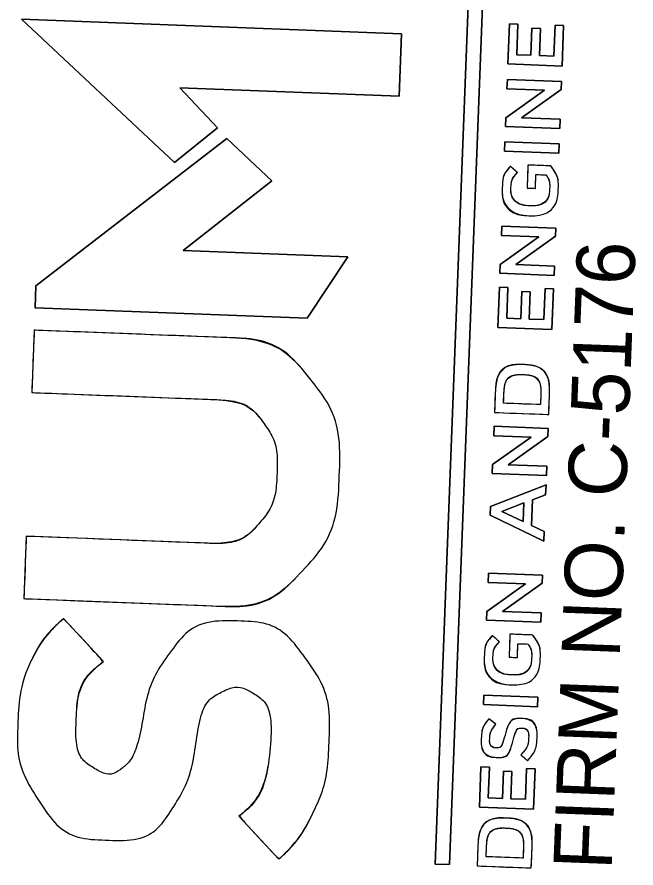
# Model space of a CAD drawing. Extents: x 1654773 to 2116434, y 680831 to 888488.
# Drawn here: x 2099592.9 to 2099858.3, y 685725.9 to 686090.8 of the extents above; entities that cross this region are included whole.
import ezdxf

# ---------------------------------------------------------------- set-up
doc = ezdxf.new("R2010")
doc.units = 0
doc.layers.add('Old_Level_3', color=7, linetype='Continuous')

msp = doc.modelspace()

# ---------------------------------------------------------------- linework, layer by layer
at = {"layer": 'Old_Level_3'}
for p, q in [((2099807.44, 686024.06), (2099804.45, 686026.77)), ((2099812.68, 686009.83), (2099812.61, 686009.84)), ((2099812.51, 686005.56), (2099812.58, 686005.56)), ((2099810.06, 685941.73), (2099810, 685941.73)), ((2099809.9, 685937.46), (2099809.97, 685937.45)), ((2099629.93, 685814.4), (2099612.81, 685832.86)), ((2099799.72, 685822.88), (2099796.74, 685825.58)), ((2099804.96, 685808.65), (2099804.89, 685808.65)), ((2099804.8, 685804.38), (2099804.86, 685804.38)), ((2099798.2, 685787.46), (2099795.2, 685789.77)), ((2099809.26, 685789.92), (2099809.19, 685789.92)), ((2099809.43, 685785.84), (2099809.5, 685785.83)), ((2099798.25, 685777.37), (2099798.18, 685777.38)), ((2099798.39, 685773.29), (2099798.45, 685773.29)), ((2099808.96, 685774.41), (2099811.79, 685771.85)), ((2099688.04, 685748.08), (2099705.17, 685729.62)), ((2099802.61, 685747.27), (2099802.54, 685747.27)), ((2099802.44, 685743), (2099802.51, 685743))]:
    msp.add_line(p, q, dxfattribs=at)
for points in [[(2099803.18, 686374.77), (2099778.35, 685727.33), (2099772.17, 685727.56), (2099797.01, 686375.01), (2099803.18, 686374.77)], [(2099797.01, 686375.01), (2099772.17, 685727.56), (2099778.35, 685727.33), (2099803.18, 686374.77), (2099797.01, 686375.01)], [(2099594.75, 686089.78), (2099757.71, 686083.53), (2099756.68, 686056.81), (2099662.69, 686060.42), (2099678.88, 686043.23), (2099660.43, 686028.35), (2099594.75, 686089.78)], [(2099660.43, 686028.35), (2099678.88, 686043.23), (2099662.69, 686060.42), (2099756.68, 686056.81), (2099757.71, 686083.53), (2099594.75, 686089.78), (2099660.43, 686028.35)], [(2099803.38, 686070.64), (2099804.04, 686087.83), (2099807.69, 686087.69), (2099807.19, 686074.57), (2099813.22, 686074.34), (2099813.67, 686085.96), (2099817.32, 686085.82), (2099816.87, 686074.2), (2099823.11, 686073.96), (2099823.62, 686087.24), (2099827.27, 686087.1), (2099826.6, 686069.75), (2099803.38, 686070.64)], [(2099826.6, 686069.75), (2099827.27, 686087.1), (2099823.62, 686087.24), (2099823.11, 686073.96), (2099816.87, 686074.2), (2099817.32, 686085.82), (2099813.67, 686085.96), (2099813.22, 686074.34), (2099807.19, 686074.57), (2099807.69, 686087.69), (2099804.04, 686087.83), (2099803.38, 686070.64), (2099826.6, 686069.75)], [(2099802.35, 686043.82), (2099802.5, 686047.6), (2099819.03, 686059.4), (2099802.97, 686060.01), (2099803.13, 686064.02), (2099826.35, 686063.13), (2099826.22, 686059.72), (2099809.21, 686047.57), (2099825.73, 686046.94), (2099825.57, 686042.93), (2099802.35, 686043.82)], [(2099825.57, 686042.93), (2099825.73, 686046.94), (2099809.21, 686047.57), (2099826.22, 686059.72), (2099826.35, 686063.13), (2099803.13, 686064.02), (2099802.97, 686060.01), (2099819.03, 686059.4), (2099802.5, 686047.6), (2099802.35, 686043.82), (2099825.57, 686042.93)], [(2099600.98, 685975.48), (2099682.8, 686038.73), (2099702.08, 686020.46), (2099664.15, 685990.59), (2099734.72, 685987.88), (2099717.29, 685961.58), (2099600.62, 685966.05), (2099600.98, 685975.48)], [(2099600.62, 685966.05), (2099717.29, 685961.58), (2099734.72, 685987.88), (2099664.15, 685990.59), (2099702.08, 686020.46), (2099682.8, 686038.73), (2099600.98, 685975.48), (2099600.62, 685966.05)], [(2099801.94, 686033.22), (2099802.1, 686037.3), (2099825.32, 686036.41), (2099825.17, 686032.33), (2099801.94, 686033.22)], [(2099825.17, 686032.33), (2099825.32, 686036.41), (2099802.1, 686037.3), (2099801.94, 686033.22), (2099825.17, 686032.33)], [(2099821.74, 686026.93), (2099811.98, 686027.31), (2099811.61, 686017.44), (2099815.15, 686017.3), (2099815.38, 686023.23), (2099819.73, 686023.06)], [(2099799.94, 685980.88), (2099800.08, 685984.65), (2099816.61, 685996.45), (2099800.56, 685997.07), (2099800.71, 686001.08), (2099823.93, 686000.19), (2099823.8, 685996.78), (2099806.79, 685984.63), (2099823.31, 685983.99), (2099823.16, 685979.99), (2099799.94, 685980.88)], [(2099823.16, 685979.99), (2099823.31, 685983.99), (2099806.79, 685984.63), (2099823.8, 685996.78), (2099823.93, 686000.19), (2099800.71, 686001.08), (2099800.56, 685997.07), (2099816.61, 685996.45), (2099800.08, 685984.65), (2099799.94, 685980.88), (2099823.16, 685979.99)], [(2099799.05, 685957.7), (2099799.71, 685974.89), (2099803.36, 685974.75), (2099802.85, 685961.63), (2099808.89, 685961.4), (2099809.34, 685973.02), (2099812.99, 685972.88), (2099812.54, 685961.26), (2099818.78, 685961.02), (2099819.29, 685974.3), (2099822.94, 685974.16), (2099822.27, 685956.81), (2099799.05, 685957.7)], [(2099822.27, 685956.81), (2099822.94, 685974.16), (2099819.29, 685974.3), (2099818.78, 685961.02), (2099812.54, 685961.26), (2099812.99, 685972.88), (2099809.34, 685973.02), (2099808.89, 685961.4), (2099802.85, 685961.63), (2099803.36, 685974.75), (2099799.71, 685974.89), (2099799.05, 685957.7), (2099822.27, 685956.81)], [(2099684.31, 685953.24), (2099600.25, 685956.46), (2099599.23, 685929.74), (2099676.15, 685926.79)], [(2099797.98, 685929.85), (2099797.65, 685921.21), (2099820.87, 685920.32), (2099821.2, 685928.96)], [(2099817.49, 685929.11), (2099817.31, 685924.54), (2099801.52, 685925.14), (2099801.69, 685929.71)], [(2099796.65, 685895.05), (2099796.79, 685898.83), (2099813.32, 685910.63), (2099797.27, 685911.24), (2099797.42, 685915.26), (2099820.64, 685914.37), (2099820.51, 685910.95), (2099803.5, 685898.8), (2099820.02, 685898.17), (2099819.87, 685894.16), (2099796.65, 685895.05)], [(2099819.87, 685894.16), (2099820.02, 685898.17), (2099803.5, 685898.8), (2099820.51, 685910.95), (2099820.64, 685914.37), (2099797.42, 685915.26), (2099797.27, 685911.24), (2099813.32, 685910.63), (2099796.79, 685898.83), (2099796.65, 685895.05), (2099819.87, 685894.16)], [(2099795.79, 685877.11), (2099795.94, 685880.89), (2099819.72, 685890.2), (2099819.55, 685885.89), (2099813.85, 685883.75), (2099813.43, 685872.79), (2099818.95, 685870.19), (2099818.79, 685866.02), (2099795.79, 685877.11)], [(2099818.79, 685866.02), (2099818.95, 685870.19), (2099813.43, 685872.79), (2099813.85, 685883.75), (2099819.55, 685885.89), (2099819.72, 685890.2), (2099795.94, 685880.89), (2099795.79, 685877.11), (2099818.79, 685866.02)], [(2099810.18, 685882.4), (2099800.74, 685878.75), (2099809.87, 685874.42), (2099810.18, 685882.4)], [(2099809.87, 685874.42), (2099800.74, 685878.75), (2099810.18, 685882.4), (2099809.87, 685874.42)], [(2099673.79, 685865.14), (2099596.86, 685868.09), (2099595.84, 685841.36), (2099679.89, 685838.14)], [(2099794.23, 685832.14), (2099794.38, 685835.91), (2099810.91, 685847.72), (2099794.85, 685848.34), (2099795.01, 685852.34), (2099818.23, 685851.45), (2099818.1, 685848.04), (2099801.09, 685835.89), (2099817.61, 685835.26), (2099817.45, 685831.25), (2099794.23, 685832.14)], [(2099817.45, 685831.25), (2099817.61, 685835.26), (2099801.09, 685835.89), (2099818.1, 685848.04), (2099818.23, 685851.45), (2099795.01, 685852.34), (2099794.85, 685848.34), (2099810.91, 685847.72), (2099794.38, 685835.91), (2099794.23, 685832.14), (2099817.45, 685831.25)], [(2099814.02, 685825.75), (2099804.27, 685826.12), (2099803.89, 685816.25), (2099807.44, 685816.12), (2099807.67, 685822.05), (2099812.01, 685821.88)], [(2099792.84, 685795.92), (2099793, 685799.99), (2099816.22, 685799.1), (2099816.07, 685795.03), (2099792.84, 685795.92)], [(2099816.07, 685795.03), (2099816.22, 685799.1), (2099793, 685799.99), (2099792.84, 685795.92), (2099816.07, 685795.03)], [(2099791.16, 685751.98), (2099791.82, 685769.17), (2099795.47, 685769.03), (2099794.96, 685755.91), (2099801, 685755.68), (2099801.45, 685767.31), (2099805.1, 685767.17), (2099804.65, 685755.54), (2099810.89, 685755.3), (2099811.4, 685768.58), (2099815.05, 685768.44), (2099814.38, 685751.09), (2099791.16, 685751.98)], [(2099814.38, 685751.09), (2099815.05, 685768.44), (2099811.4, 685768.58), (2099810.89, 685755.3), (2099804.65, 685755.54), (2099805.1, 685767.17), (2099801.45, 685767.31), (2099801, 685755.68), (2099794.96, 685755.91), (2099795.47, 685769.03), (2099791.82, 685769.17), (2099791.16, 685751.98), (2099814.38, 685751.09)], [(2099790.52, 685735.4), (2099790.19, 685726.75), (2099813.41, 685725.86), (2099813.74, 685734.51)], [(2099810.03, 685734.65), (2099809.85, 685730.08), (2099794.06, 685730.68), (2099794.24, 685735.25)]]:
    msp.add_lwpolyline(points, dxfattribs=at)
for points, degree in [([(2099812.58, 686005.56), (2099812.58, 686005.56), (2099812.51, 686005.56), (2099812.51, 686005.56), (2099806.01, 686005.81), (2099800.69, 686010.99), (2099800.96, 686017.98), (2099801.12, 686022.02), (2099802.34, 686024.46), (2099804.45, 686026.77), (2099804.45, 686026.77), (2099807.44, 686024.06), (2099807.44, 686024.06), (2099805.85, 686022.34), (2099804.82, 686020.62), (2099804.7, 686017.67), (2099804.54, 686013.4), (2099808.16, 686010.01), (2099812.61, 686009.84), (2099812.61, 686009.84), (2099812.68, 686009.83), (2099812.68, 686009.83), (2099817.45, 686009.65), (2099821.09, 686012.66), (2099821.27, 686017.4), (2099821.36, 686019.58), (2099820.73, 686021.6), (2099819.73, 686023.06), (2099819.73, 686023.06), (2099815.38, 686023.23), (2099815.38, 686023.23), (2099815.38, 686023.23), (2099815.15, 686017.3), (2099815.15, 686017.3), (2099815.15, 686017.3), (2099811.61, 686017.44), (2099811.61, 686017.44), (2099811.61, 686017.44), (2099811.98, 686027.31), (2099811.98, 686027.31), (2099811.98, 686027.31), (2099821.74, 686026.93), (2099821.74, 686026.93), (2099823.61, 686024.58), (2099825.14, 686021.23), (2099824.98, 686017.12), (2099824.7, 686009.87), (2099819.35, 686005.3), (2099812.58, 686005.56)], 3), ([(2099804.45, 686026.77), (2099802.34, 686024.46), (2099801.12, 686022.02), (2099800.96, 686017.98), (2099800.69, 686010.99), (2099806.01, 686005.81), (2099812.51, 686005.56)], 3), ([(2099812.61, 686009.84), (2099808.16, 686010.01), (2099804.54, 686013.4), (2099804.7, 686017.67), (2099804.82, 686020.62), (2099805.85, 686022.34), (2099807.44, 686024.06)], 3), ([(2099812.58, 686005.56), (2099819.35, 686005.3), (2099824.7, 686009.87), (2099824.98, 686017.12), (2099825.14, 686021.23), (2099823.61, 686024.58), (2099821.74, 686026.93)], 3), ([(2099819.73, 686023.06), (2099820.73, 686021.6), (2099821.36, 686019.58), (2099821.27, 686017.4), (2099821.09, 686012.66), (2099817.45, 686009.65), (2099812.68, 686009.83)], 3), ([(2099596.86, 685868.09), (2099596.86, 685868.09), (2099673.79, 685865.14), (2099673.79, 685865.14), (2099683.89, 685864.75), (2099691.42, 685867.49), (2099696.4, 685873.23), (2099701.38, 685878.98), (2099704.04, 685886.33), (2099704.38, 685895.22), (2099704.72, 685904.11), (2099702.62, 685911.28), (2099698.09, 685917.39), (2099693.57, 685923.49), (2099686.26, 685926.41), (2099676.15, 685926.79), (2099676.15, 685926.79), (2099599.23, 685929.74), (2099599.23, 685929.74), (2099599.23, 685929.74), (2099600.25, 685956.46), (2099600.25, 685956.46), (2099600.25, 685956.46), (2099684.31, 685953.24), (2099684.31, 685953.24), (2099697.97, 685952.72), (2099709.34, 685947.12), (2099718.42, 685935.78), (2099727.49, 685924.45), (2099731.73, 685910.66), (2099731.09, 685894.07), (2099730.45, 685877.47), (2099725.17, 685863.86), (2099715.25, 685853.27), (2099705.33, 685842.66), (2099693.55, 685837.62), (2099679.89, 685838.14), (2099679.89, 685838.14), (2099595.84, 685841.36), (2099595.84, 685841.36), (2099595.84, 685841.36), (2099596.86, 685868.09), (2099596.86, 685868.09)], 3), ([(2099679.89, 685838.14), (2099693.55, 685837.62), (2099705.33, 685842.66), (2099715.25, 685853.27), (2099725.17, 685863.86), (2099730.45, 685877.47), (2099731.09, 685894.07), (2099731.73, 685910.66), (2099727.49, 685924.45), (2099718.42, 685935.78), (2099709.34, 685947.12), (2099697.97, 685952.72), (2099684.31, 685953.24)], 3), ([(2099797.65, 685921.21), (2099797.65, 685921.21), (2099797.98, 685929.85), (2099797.98, 685929.85), (2099798.26, 685937.14), (2099803.46, 685941.98), (2099810, 685941.73), (2099810, 685941.73), (2099810.06, 685941.73), (2099810.06, 685941.73), (2099816.6, 685941.48), (2099821.48, 685936.25), (2099821.2, 685928.96), (2099821.2, 685928.96), (2099820.87, 685920.32), (2099820.87, 685920.32), (2099820.87, 685920.32), (2099797.65, 685921.21), (2099797.65, 685921.21)], 3), ([(2099810, 685941.73), (2099803.46, 685941.98), (2099798.26, 685937.14), (2099797.98, 685929.85)], 2), ([(2099821.2, 685928.96), (2099821.48, 685936.25), (2099816.6, 685941.48), (2099810.06, 685941.73)], 2), ([(2099801.52, 685925.14), (2099801.52, 685925.14), (2099817.31, 685924.54), (2099817.31, 685924.54), (2099817.31, 685924.54), (2099817.49, 685929.11), (2099817.49, 685929.11), (2099817.67, 685933.98), (2099814.51, 685937.28), (2099809.97, 685937.45), (2099809.97, 685937.45), (2099809.9, 685937.46), (2099809.9, 685937.46), (2099805.35, 685937.63), (2099801.88, 685934.58), (2099801.69, 685929.71), (2099801.69, 685929.71), (2099801.52, 685925.14), (2099801.52, 685925.14)], 3), ([(2099801.69, 685929.71), (2099801.88, 685934.58), (2099805.35, 685937.63), (2099809.9, 685937.46)], 2), ([(2099809.97, 685937.45), (2099814.51, 685937.28), (2099817.67, 685933.98), (2099817.49, 685929.11)], 2), ([(2099676.15, 685926.79), (2099686.26, 685926.41), (2099693.57, 685923.49), (2099698.09, 685917.39), (2099702.62, 685911.28), (2099704.72, 685904.11), (2099704.38, 685895.22), (2099704.04, 685886.33), (2099701.38, 685878.98), (2099696.4, 685873.23), (2099691.42, 685867.49), (2099683.89, 685864.75), (2099673.79, 685865.14)], 3), ([(2099598.73, 685814.26), (2099601.95, 685820.97), (2099606.64, 685827.17), (2099612.81, 685832.86), (2099612.81, 685832.86), (2099629.93, 685814.4), (2099629.93, 685814.4), (2099622.59, 685808.75), (2099618.7, 685800.6), (2099618.3, 685789.92), (2099617.89, 685779.26), (2099620.15, 685772.34), (2099625.09, 685769.18), (2099630.02, 685766.03), (2099634.32, 685765.87), (2099637.99, 685768.69), (2099641.67, 685771.52), (2099644.6, 685778.23), (2099646.79, 685788.83), (2099648.41, 685800.04), (2099652.51, 685810.13), (2099659.1, 685819.07), (2099665.68, 685828.02), (2099675.8, 685832.22), (2099689.46, 685831.7), (2099700.15, 685831.29), (2099709.16, 685826.04), (2099716.49, 685815.94), (2099723.84, 685805.84), (2099727.26, 685794.26), (2099726.76, 685781.22), (2099726.29, 685768.84), (2099724.11, 685758.56), (2099720.23, 685750.4), (2099716.34, 685742.24), (2099711.32, 685735.31), (2099705.17, 685729.62), (2099705.17, 685729.62), (2099688.04, 685748.08), (2099688.04, 685748.08), (2099695.39, 685753.73), (2099699.93, 685763.65), (2099701.66, 685777.82), (2099702.11, 685789.68), (2099699.87, 685797.17), (2099694.94, 685800.3), (2099690.01, 685803.42), (2099684.96, 685803.61), (2099679.8, 685800.88), (2099674.64, 685798.14), (2099671.25, 685790.86), (2099669.6, 685779.05), (2099668.01, 685768.43), (2099664.37, 685758.78), (2099658.68, 685750.09), (2099653, 685741.41), (2099643.63, 685737.31), (2099630.57, 685737.81), (2099618.76, 685738.27), (2099609.47, 685743.69), (2099602.7, 685754.07), (2099595.93, 685764.44), (2099592.76, 685774.96), (2099593.16, 685785.63), (2099593.64, 685798.02), (2099595.48, 685807.56), (2099598.73, 685814.26)], 3), ([(2099612.81, 685832.86), (2099606.64, 685827.17), (2099601.95, 685820.97), (2099598.73, 685814.26)], 2), ([(2099705.17, 685729.62), (2099711.32, 685735.31), (2099716.34, 685742.24), (2099720.23, 685750.4), (2099724.11, 685758.56), (2099726.29, 685768.84), (2099726.76, 685781.22), (2099727.26, 685794.26), (2099723.84, 685805.84), (2099716.49, 685815.94), (2099709.16, 685826.04), (2099700.15, 685831.29), (2099689.46, 685831.7), (2099675.8, 685832.22), (2099665.68, 685828.02), (2099659.1, 685819.07), (2099652.51, 685810.13), (2099648.41, 685800.04), (2099646.79, 685788.83), (2099644.6, 685778.23), (2099641.67, 685771.52), (2099637.99, 685768.69), (2099634.32, 685765.87), (2099630.02, 685766.03), (2099625.09, 685769.18), (2099620.15, 685772.34), (2099617.89, 685779.26), (2099618.3, 685789.92), (2099618.7, 685800.6), (2099622.59, 685808.75), (2099629.93, 685814.4)], 3), ([(2099804.86, 685804.38), (2099804.86, 685804.38), (2099804.8, 685804.38), (2099804.8, 685804.38), (2099798.29, 685804.63), (2099792.98, 685809.81), (2099793.25, 685816.79), (2099793.4, 685820.84), (2099794.62, 685823.28), (2099796.74, 685825.58), (2099796.74, 685825.58), (2099799.72, 685822.88), (2099799.72, 685822.88), (2099798.13, 685821.15), (2099797.1, 685819.44), (2099796.99, 685816.49), (2099796.82, 685812.21), (2099800.45, 685808.82), (2099804.89, 685808.65), (2099804.89, 685808.65), (2099804.96, 685808.65), (2099804.96, 685808.65), (2099809.74, 685808.47), (2099813.37, 685811.48), (2099813.56, 685816.22), (2099813.64, 685818.4), (2099813.02, 685820.41), (2099812.01, 685821.88), (2099812.01, 685821.88), (2099807.67, 685822.05), (2099807.67, 685822.05), (2099807.67, 685822.05), (2099807.44, 685816.12), (2099807.44, 685816.12), (2099807.44, 685816.12), (2099803.89, 685816.25), (2099803.89, 685816.25), (2099803.89, 685816.25), (2099804.27, 685826.12), (2099804.27, 685826.12), (2099804.27, 685826.12), (2099814.02, 685825.75), (2099814.02, 685825.75), (2099815.89, 685823.39), (2099817.42, 685820.05), (2099817.27, 685815.94), (2099816.99, 685808.69), (2099811.63, 685804.12), (2099804.86, 685804.38)], 3), ([(2099796.74, 685825.58), (2099794.62, 685823.28), (2099793.4, 685820.84), (2099793.25, 685816.79), (2099792.98, 685809.81), (2099798.29, 685804.63), (2099804.8, 685804.38)], 3), ([(2099804.86, 685804.38), (2099811.63, 685804.12), (2099816.99, 685808.69), (2099817.27, 685815.94), (2099817.42, 685820.05), (2099815.89, 685823.39), (2099814.02, 685825.75)], 3), ([(2099804.89, 685808.65), (2099800.45, 685808.82), (2099796.82, 685812.21), (2099796.99, 685816.49), (2099797.1, 685819.44), (2099798.13, 685821.15), (2099799.72, 685822.88)], 3), ([(2099812.01, 685821.88), (2099813.02, 685820.41), (2099813.64, 685818.4), (2099813.56, 685816.22), (2099813.37, 685811.48), (2099809.74, 685808.47), (2099804.96, 685808.65)], 3), ([(2099598.73, 685814.26), (2099595.48, 685807.56), (2099593.64, 685798.02), (2099593.16, 685785.63), (2099592.76, 685774.96), (2099595.93, 685764.44), (2099602.7, 685754.07), (2099609.47, 685743.69), (2099618.76, 685738.27), (2099630.57, 685737.81), (2099643.63, 685737.31), (2099653, 685741.41), (2099658.68, 685750.09), (2099664.37, 685758.78), (2099668.01, 685768.43), (2099669.6, 685779.05), (2099671.25, 685790.86), (2099674.64, 685798.14), (2099679.8, 685800.88), (2099684.96, 685803.61), (2099690.01, 685803.42), (2099694.94, 685800.3), (2099699.87, 685797.17), (2099702.11, 685789.68), (2099701.66, 685777.82), (2099699.93, 685763.65), (2099695.39, 685753.73), (2099688.04, 685748.08)], 3), ([(2099811.79, 685771.85), (2099811.79, 685771.85), (2099808.96, 685774.41), (2099808.96, 685774.41), (2099810.97, 685776.56), (2099812.15, 685778.76), (2099812.26, 685781.62), (2099812.36, 685784.13), (2099811.22, 685785.77), (2099809.5, 685785.83), (2099809.5, 685785.83), (2099809.43, 685785.84), (2099809.43, 685785.84), (2099807.78, 685785.9), (2099806.84, 685785.01), (2099805.68, 685780.74), (2099804.3, 685775.85), (2099802.73, 685773.13), (2099798.45, 685773.29), (2099798.45, 685773.29), (2099798.39, 685773.29), (2099798.39, 685773.29), (2099794.41, 685773.44), (2099791.78, 685776.86), (2099791.96, 685781.46), (2099792.09, 685784.84), (2099793.22, 685787.48), (2099795.2, 685789.77), (2099795.2, 685789.77), (2099798.2, 685787.46), (2099798.2, 685787.46), (2099796.56, 685785.43), (2099795.65, 685783.38), (2099795.57, 685781.26), (2099795.48, 685778.88), (2099796.65, 685777.44), (2099798.18, 685777.38), (2099798.18, 685777.38), (2099798.25, 685777.37), (2099798.25, 685777.37), (2099800.04, 685777.31), (2099800.87, 685778.34), (2099802.11, 685782.76), (2099803.49, 685787.62), (2099805.34, 685790.07), (2099809.19, 685789.92), (2099809.19, 685789.92), (2099809.26, 685789.92), (2099809.26, 685789.92), (2099813.6, 685789.75), (2099816.06, 685786.25), (2099815.87, 685781.38), (2099815.74, 685777.83), (2099814.38, 685774.54), (2099811.79, 685771.85)], 3), ([(2099795.2, 685789.77), (2099793.22, 685787.48), (2099792.09, 685784.84), (2099791.96, 685781.46), (2099791.78, 685776.86), (2099794.41, 685773.44), (2099798.39, 685773.29)], 3), ([(2099798.18, 685777.38), (2099796.65, 685777.44), (2099795.48, 685778.88), (2099795.57, 685781.26), (2099795.65, 685783.38), (2099796.56, 685785.43), (2099798.2, 685787.46)], 3), ([(2099809.19, 685789.92), (2099805.34, 685790.07), (2099803.49, 685787.62), (2099802.11, 685782.76), (2099800.87, 685778.34), (2099800.04, 685777.31), (2099798.25, 685777.37)], 3), ([(2099811.79, 685771.85), (2099814.38, 685774.54), (2099815.74, 685777.83), (2099815.87, 685781.38), (2099816.06, 685786.25), (2099813.6, 685789.75), (2099809.26, 685789.92)], 3), ([(2099798.45, 685773.29), (2099802.73, 685773.13), (2099804.3, 685775.85), (2099805.68, 685780.74), (2099806.84, 685785.01), (2099807.78, 685785.9), (2099809.43, 685785.84)], 3), ([(2099809.5, 685785.83), (2099811.22, 685785.77), (2099812.36, 685784.13), (2099812.26, 685781.62), (2099812.15, 685778.76), (2099810.97, 685776.56), (2099808.96, 685774.41)], 3), ([(2099790.19, 685726.75), (2099790.19, 685726.75), (2099790.52, 685735.4), (2099790.52, 685735.4), (2099790.8, 685742.68), (2099796, 685747.52), (2099802.54, 685747.27), (2099802.54, 685747.27), (2099802.61, 685747.27), (2099802.61, 685747.27), (2099809.14, 685747.02), (2099814.02, 685741.79), (2099813.74, 685734.51), (2099813.74, 685734.51), (2099813.41, 685725.86), (2099813.41, 685725.86), (2099813.41, 685725.86), (2099790.19, 685726.75), (2099790.19, 685726.75)], 3), ([(2099802.54, 685747.27), (2099796, 685747.52), (2099790.8, 685742.68), (2099790.52, 685735.4)], 2), ([(2099813.74, 685734.51), (2099814.02, 685741.79), (2099809.14, 685747.02), (2099802.61, 685747.27)], 2), ([(2099794.06, 685730.68), (2099794.06, 685730.68), (2099809.85, 685730.08), (2099809.85, 685730.08), (2099809.85, 685730.08), (2099810.03, 685734.65), (2099810.03, 685734.65), (2099810.22, 685739.52), (2099807.05, 685742.82), (2099802.51, 685743), (2099802.51, 685743), (2099802.44, 685743), (2099802.44, 685743), (2099797.9, 685743.17), (2099794.42, 685740.12), (2099794.24, 685735.25), (2099794.24, 685735.25), (2099794.06, 685730.68), (2099794.06, 685730.68)], 3), ([(2099794.24, 685735.25), (2099794.42, 685740.12), (2099797.9, 685743.17), (2099802.44, 685743)], 2), ([(2099802.51, 685743), (2099807.05, 685742.82), (2099810.22, 685739.52), (2099810.03, 685734.65)], 2)]:
    msp.add_open_spline(points, degree=degree, dxfattribs=at)

# ---------------------------------------------------------------- texts
msp.add_text('FIRM NO. C-5176', height=25.0121, rotation=87.8037, dxfattribs=at).set_placement((2099847.82, 685724.8))

doc.saveas('drawing.dxf')
